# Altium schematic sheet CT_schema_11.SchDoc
size 252 x 159 mm
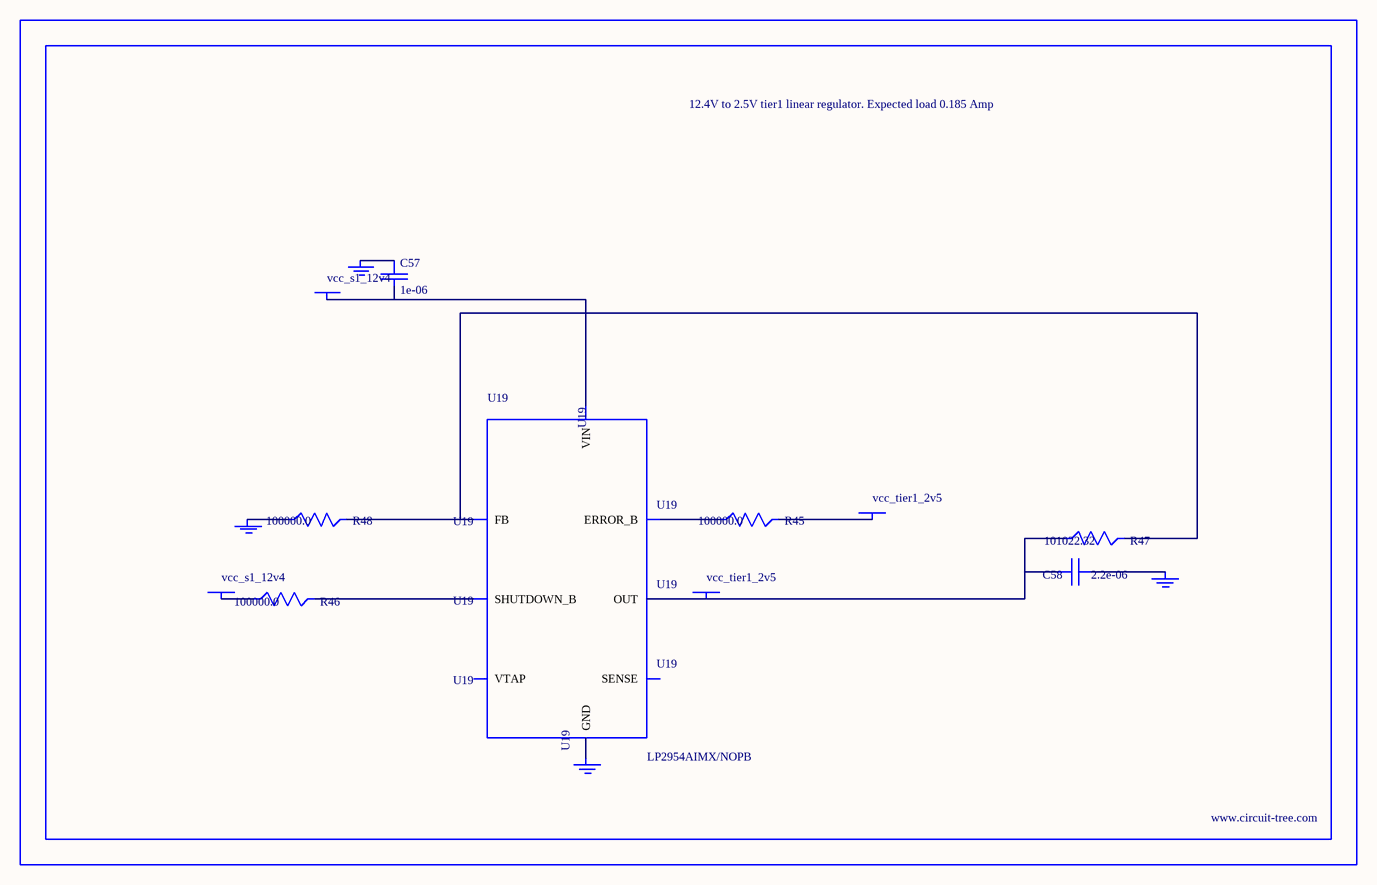
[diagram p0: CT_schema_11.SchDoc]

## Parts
BORDER10  (no value)
C57  1e-06  [EXV-9B]
C58  2.2e-06  [EXV-9B]
GND_INSTANCE_10_0  (no value)
GND_INSTANCE_10_1  (no value)
GND_INSTANCE_10_2  (no value)
GND_INSTANCE_10_3  (no value)
POWER_INSTANCE_10_0  vcc_s1_12v4
POWER_INSTANCE_10_1  vcc_tier1_2v5
POWER_INSTANCE_10_2  vcc_s1_12v4
POWER_INSTANCE_10_3  vcc_tier1_2v5
R45  100000.0  [R0603]
R46  100000.0  [R0603]
R47  101022.32  [R0603]
R48  100000.0  [R0603]
U19  LP2954AIMX/NOPB  [LP2954]

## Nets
NetC57_1: C57.1 GND_INSTANCE_10_2.0(GND)
NetC57_2: C57.2 POWER_INSTANCE_10_2.0(PWR) U19.8(VIN)
NetC58_1: C58.1 GND_INSTANCE_10_0.0(GND)
NetC58_2: C58.2 POWER_INSTANCE_10_3.0(PWR) R47.1 U19.1(OUT)
NetGND_INSTANCE_10_1_0: GND_INSTANCE_10_1.0(GND) R48.1
NetGND_INSTANCE_10_3_0: GND_INSTANCE_10_3.0(GND) U19.4(GND)
NetPOWER_INSTANCE_10_0_0: POWER_INSTANCE_10_0.0(PWR) R46.1
NetPOWER_INSTANCE_10_1_0: POWER_INSTANCE_10_1.0(PWR) R45.2
NetR45_1: R45.1 U19.5(ERROR_B)
NetR46_2: R46.2 U19.3(SHUTDOWN_B)
NetR47_2: R47.2 R48.2 U19.7(FB)

Not connected (* = marked no-connect by the designer): U19 2(SENSE) 6(VTAP)

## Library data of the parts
BORDER10 = BORDER_PAGE10
C57 = EDK105M050A9BAA
C58 = EDK225M050A9BAA
GND_INSTANCE_10_0-GND_INSTANCE_10_3 = GND
POWER_INSTANCE_10_0-POWER_INSTANCE_10_3 = PWR
R45 R46 R48 = RC0603JR-07100KL
R47 = R47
